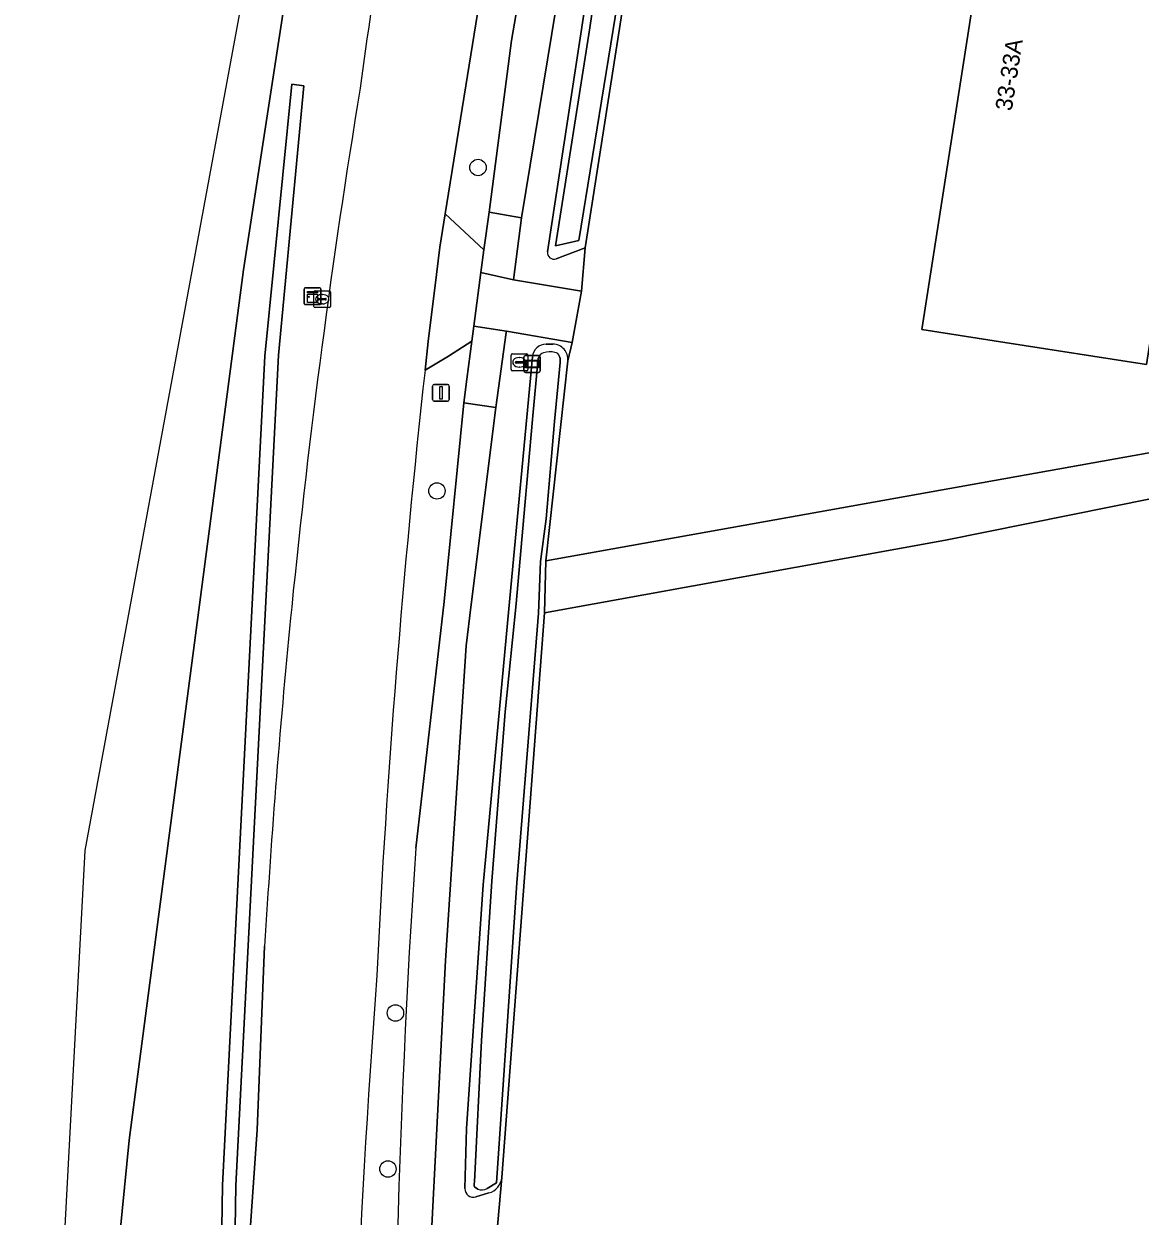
# Model space of a CAD drawing. Extents: x 162510 to 163918, y 388494 to 389774.
# Drawn here: x 162529.3 to 162595.9, y 389141.7 to 389212.7 of the extents above; entities that cross this region are included whole.
import ezdxf

# ---------------------------------------------------------------- set-up
doc = ezdxf.new("R2010")
doc.units = 0
for name, color, linetype in [('IMGEO_Berm_groen', 7, 'Continuous'), ('IMGEO_Boom', 7, 'Continuous'), ('IMGEO_Brandkraan', 7, 'Continuous'), ('IMGEO_Erf', 7, 'Continuous'), ('IMGEO_Fietspad_gesloten', 7, 'Continuous'), ('IMGEO_Fietspad_open', 7, 'Continuous'), ('IMGEO_Grasland_agrarisch', 7, 'Continuous'), ('IMGEO_Groenvoorziening', 7, 'Continuous'), ('IMGEO_Haag', 7, 'Continuous'), ('IMGEO_Kast', 7, 'Continuous'), ('IMGEO_Lichtmast', 7, 'Continuous'), ('IMGEO_Oever', 7, 'Continuous'), ('IMGEO_Pand', 7, 'Continuous'), ('IMGEO_Pand_nummerreeks', 7, 'Continuous'), ('IMGEO_Rijbaan_lokaal_gesloten', 7, 'Continuous'), ('IMGEO_Rijbaan_lokaal_open', 7, 'Continuous'), ('IMGEO_Rijbaan_regionaal_gesloten', 7, 'Continuous'), ('IMGEO_Rioolput', 7, 'Continuous'), ('IMGEO_Verklikker', 7, 'Continuous'), ('IMGEO_Voetpad_open', 7, 'Continuous'), ('IMGEO_Waterloop', 7, 'Continuous')]:
    doc.layers.add(name, color=color, linetype=linetype)

msp = doc.modelspace()

# ---------------------------------------------------------------- linework, layer by layer
at = {"layer": 'IMGEO_Berm_groen'}
for points in [[(162578.291, 389339.209), (162562.528, 389250), (162558.728, 389227.691), (162557.59, 389221.012), (162554.439, 389201.41), (162556.746, 389199.277), (162557.059, 389201.504), (162558.393, 389211.739), (162561.148, 389227.73), (162564.984, 389250), (162573.643, 389300.337), (162582.8, 389349.853), (162587.308, 389370.06), (162590.51, 389382)], [(162566.487, 389328.537), (162555.541, 389271.647), (162551.509, 389250), (162549.518, 389239.311), (162547.006, 389227.506), (162546.737, 389226.244), (162542.42, 389198.072), (162535.591, 389146.194), (162532.774, 389117.585), (162532.37, 389111.58), (162531.945, 389105.576), (162531.883, 389104.725), (162542.611, 389104.527), (162542.248, 389126.195), (162542.247, 389126.251), (162542.46, 389135.692), (162543.227, 389146.814)], [(162552.68, 389163.6), (162554.369, 389178.31), (162555.538, 389190.147), (162555.728, 389191.566), (162556.029, 389193.817), (162554.628, 389192.923), (162553.237, 389192.101)], [(162543.227, 389146.814), (162543.676, 389157.755)]]:
    msp.add_lwpolyline(points, dxfattribs=at)
msp.add_lwpolyline([(162545.297, 389209.14), (162546.015, 389209.041), (162544.5, 389192.998), (162541.965, 389143.494), (162541.527, 389115.616), (162541.714, 389107.47), (162540.915, 389107.452), (162540.727, 389115.614), (162541.165, 389143.52), (162543.695, 389192.921)], close=True, dxfattribs=at)
for centre, radius, start, end in [((163016.869, 389145.516), 471.78, 169.98165, 172.27762), ((163041.938, 389128.226), 499.136, 170.69731, 174.28081), ((163134.343, 389127.616), 584.673, 173.667779, 177.216056), ((163042.455, 389128.167), 499.656, 174.28008, 176.6052), ((163131.139, 389124.822), 579.757, 176.164852, 181.065754), ((163178.789, 389108.905), 630.192, 175.71308, 179.850847)]:
    msp.add_arc(centre, radius, start, end, dxfattribs=at)
at = {"layer": 'IMGEO_Boom'}
for centre in [(162556.393, 389204.175), (162553.946, 389184.898), (162551.472, 389153.78), (162551.024, 389144.481)]:
    msp.add_circle(centre, 0.489, dxfattribs=at)
at = {"layer": 'IMGEO_Brandkraan'}
for p, q in [((162558.36, 389192.136), (162558.36, 389192.988)), ((162558.435, 389193.062), (162559.287, 389193.062)), ((162558.662, 389192.605), (162559.06, 389192.605)), ((162558.848, 389192.842), (162558.873, 389192.842)), ((162559.361, 389192.988), (162559.361, 389192.136)), ((162559.287, 389192.062), (162558.435, 389192.062)), ((162558.619, 389192.556), (162558.619, 389192.568)), ((162559.057, 389192.519), (162558.659, 389192.519)), ((162558.871, 389192.282), (162558.846, 389192.282)), ((162559.103, 389192.568), (162559.103, 389192.556))]:
    msp.add_line(p, q, dxfattribs=at)
for points in [[(162558.36, 389192.136), (162558.36, 389192.988)], [(162558.435, 389193.062), (162559.287, 389193.062)], [(162559.361, 389192.988), (162559.361, 389192.136)], [(162559.287, 389192.062), (162558.435, 389192.062)]]:
    msp.add_lwpolyline(points, dxfattribs=at)
for centre, radius, start, end in [((162558.437, 389192.986), 0.0765, 91.55205, 178.44795), ((162558.437, 389192.986), 0.0765, 91.55205, 178.44795), ((162558.659, 389192.565), 0.0403, 85.87752, 175.75265), ((162559.064, 389192.567), 0.0386, 1.73085, 96.63898), ((162559.285, 389192.986), 0.0765, 1.55205, 88.44795), ((162559.285, 389192.986), 0.0765, 1.55205, 88.44795), ((162558.437, 389192.138), 0.0765, 181.55205, 268.44795), ((162558.437, 389192.138), 0.0765, 181.55205, 268.44795), ((162558.656, 389192.555), 0.0366, 178.93798, 274.71019), ((162559.06, 389192.562), 0.043, 264.86636, 352.45326), ((162559.285, 389192.138), 0.0765, 271.55205, 358.44795), ((162559.285, 389192.138), 0.0765, 271.55205, 358.44795)]:
    msp.add_arc(centre, radius, start, end, dxfattribs=at)
for centre, major_axis, ratio, start_param, end_param in [((162558.847, 389192.562), (-0.387, 0.002), 0.722429, 4.712389, 7.853982), ((162558.872, 389192.562), (-0.39, 0.002), 0.717154, 1.570796, 4.712389)]:
    msp.add_ellipse(centre, major_axis=major_axis, ratio=ratio, start_param=start_param, end_param=end_param, dxfattribs=at)
at = {"layer": 'IMGEO_Erf'}
msp.add_lwpolyline([(162571, 389230.043), (162570.831, 389229.366), (162570.5, 389228.374), (162570.367, 389228.01), (162569.475, 389228.043), (162568.35, 389227.448), (162567.424, 389226.985), (162567.013, 389226.448), (162562.784, 389199.385), (162562.558, 389196.812), (162562.318, 389195.488), (162562, 389193.735), (162561.745, 389192.655), (162560.443, 389180.721), (162604.045, 389188.547), (162613.107, 389191.215), (162635.908, 389194.267), (162680.291, 389202.531), (162722.247, 389210.612)], dxfattribs=at)
msp.add_lwpolyline([(162597.194, 389226.557), (162596.027, 389219.078), (162600.29, 389218.412), (162596.235, 389192.428), (162587.795, 389193.746), (162582.854, 389194.517), (162588.077, 389227.98), (162593.018, 389227.209)], close=True, dxfattribs=at)
at = {"layer": 'IMGEO_Fietspad_gesloten'}
msp.add_lwpolyline([(162590.51, 389382), (162587.308, 389370.06), (162582.8, 389349.853), (162573.643, 389300.337), (162564.984, 389250), (162561.148, 389227.73), (162558.393, 389211.739), (162557.059, 389201.504), (162558.98, 389201.185), (162563.35, 389227.764), (162563.969, 389231.546), (162564.383, 389234.079), (162566.987, 389250), (162579.655, 389322.796), (162581.07, 389329.832)], dxfattribs=at)
at = {"layer": 'IMGEO_Fietspad_open'}
msp.add_lwpolyline([(162558.98, 389201.185), (162557.059, 389201.504), (162556.746, 389199.277), (162556.555, 389197.917), (162558.504, 389197.478)], close=True, dxfattribs=at)
at = {"layer": 'IMGEO_Grasland_agrarisch'}
msp.add_lwpolyline([(162633.62, 389150.066), (162636.055, 389150.69), (162626.453, 389178.999), (162610.009, 389176.591), (162608.213, 389177.358), (162607.384, 389182.013), (162611.509, 389182.748), (162693.72, 389197.466), (162693.057, 389199.699), (162692.096, 389200.77), (162690.574, 389201.26), (162688.086, 389201.653), (162681.156, 389201.063), (162646.025, 389193.654), (162631.764, 389190.832), (162601.502, 389185.449), (162584.261, 389181.971), (162560.36, 389177.64), (162557.815, 389143.978), (162557.257, 389137.711), (162556.609, 389127.989), (162616.111, 389137.29), (162618.597, 389150.697), (162631.291, 389155.256)], close=True, dxfattribs=at)
at = {"layer": 'IMGEO_Groenvoorziening'}
for points in [[(162564.611, 389225.821), (162564.071, 389225.902), (162564.186, 389226.474), (162564.448, 389227.782), (162564.751, 389229.289), (162564.874, 389229.901), (162565.043, 389230.722), (162567.064, 389230.691), (162567.08, 389231.355), (162563.969, 389231.546), (162563.35, 389227.764), (162558.98, 389201.185), (162558.504, 389197.478), (162562.558, 389196.812), (162562.784, 389199.385), (162561.057, 389198.73)], [(162560.539, 389199.157), (162564.611, 389225.821)], [(162561.745, 389192.655), (162562, 389193.735), (162558.092, 389194.43), (162558.079, 389194.332), (162557.463, 389189.87), (162555.979, 389178.13), (162555.679, 389175.667), (162554.458, 389156.905), (162553.417, 389136.844), (162553.297, 389118.241), (162553.487, 389105.712), (162555.095, 389103.283), (162557.496, 389100.727), (162556.896, 389119.432)], [(162560.456, 389193.643), (162560.862, 389193.642)], [(162555.615, 389143.313), (162555.707, 389146.903), (162556.703, 389161.423), (162558.236, 389177.877), (162559.635, 389192.896)], [(162555.192, 389128.065), (162555.678, 389138.001), (162556.478, 389138.5), (162557.162, 389138.087), (162557.257, 389137.711), (162557.815, 389143.978)], [(162557.046, 389143.051), (162556.262, 389142.817)]]:
    msp.add_lwpolyline(points, dxfattribs=at)
msp.add_lwpolyline([(162546.015, 389209.041), (162545.297, 389209.14), (162543.695, 389192.921), (162541.165, 389143.52), (162540.727, 389115.614), (162540.915, 389107.452), (162541.714, 389107.47), (162541.527, 389115.616), (162541.965, 389143.494), (162544.5, 389192.998)], close=True, dxfattribs=at)
for centre, radius, start, end in [((162560.926, 389199.099), 0.391, 171.47328, 289.52754), ((162560.453, 389192.822), 0.821, 89.78523, 174.81076), ((162560.86, 389192.752), 0.89, 353.73945, 89.89411), ((162556.736, 389144.091), 1.085, 286.60113, 354.04354), ((162556.118, 389143.3), 0.504, 178.47715, 286.57421)]:
    msp.add_arc(centre, radius, start, end, dxfattribs=at)
at = {"layer": 'IMGEO_Haag'}
msp.add_lwpolyline([(162546.015, 389209.041), (162545.297, 389209.14), (162543.695, 389192.921), (162541.165, 389143.52), (162540.727, 389115.614), (162540.915, 389107.452), (162541.714, 389107.47), (162541.527, 389115.616), (162541.965, 389143.494), (162544.5, 389192.998)], close=True, dxfattribs=at)
at = {"layer": 'IMGEO_Kast'}
for p, q in [((162546.027, 389196.078), (162546.027, 389196.919)), ((162546.027, 389196.919), (162546.027, 389196.078)), ((162546.102, 389197.003), (162546.943, 389197.003)), ((162546.943, 389197.003), (162546.102, 389197.003)), ((162547.027, 389196.928), (162547.027, 389196.087)), ((162547.027, 389196.087), (162547.027, 389196.928)), ((162546.952, 389196.003), (162546.111, 389196.003)), ((162546.111, 389196.003), (162546.952, 389196.003))]:
    msp.add_line(p, q, dxfattribs=at)
for points in [[(162546.222, 389196.793), (162546.822, 389196.793), (162546.822, 389196.708), (162546.222, 389196.708), (162546.222, 389196.793)], [(162546.222, 389196.618), (162546.822, 389196.618), (162546.822, 389196.129), (162546.222, 389196.129), (162546.222, 389196.618)]]:
    msp.add_lwpolyline(points, dxfattribs=at)
msp.add_circle((162546.306, 389196.467), 0.0377, dxfattribs=at)
for centre, start, end in [((162546.105, 389196.925), 92.4484, 184.28452), ((162546.105, 389196.925), 92.4484, 184.28452), ((162546.949, 389196.925), 2.4484, 94.28452), ((162546.949, 389196.925), 2.4484, 94.28452), ((162546.105, 389196.081), 182.4484, 274.28452), ((162546.105, 389196.081), 182.4484, 274.28452), ((162546.949, 389196.081), 272.4484, 4.28452), ((162546.949, 389196.081), 272.4484, 4.28452)]:
    msp.add_arc(centre, 0.0779, start, end, dxfattribs=at)
at = {"layer": 'IMGEO_Lichtmast'}
for p, q in [((162553.789, 389191.241), (162554.579, 389191.241)), ((162554.579, 389191.241), (162553.789, 389191.241)), ((162553.689, 389190.341), (162553.689, 389191.141)), ((162553.689, 389191.141), (162553.689, 389190.341)), ((162554.679, 389191.141), (162554.679, 389190.341)), ((162554.679, 389190.341), (162554.679, 389191.141)), ((162554.579, 389190.241), (162553.789, 389190.241)), ((162553.789, 389190.241), (162554.579, 389190.241))]:
    msp.add_line(p, q, dxfattribs=at)
msp.add_lwpolyline([(162554.109, 389191.116), (162554.259, 389191.116), (162554.259, 389190.366), (162554.109, 389190.366), (162554.109, 389191.116)], dxfattribs=at)
for centre, start, end in [((162553.789, 389191.141), 90, 180), ((162553.789, 389191.141), 90, 180), ((162554.579, 389191.141), 0, 90), ((162554.579, 389191.141), 360, 90), ((162553.789, 389190.341), 180, 270), ((162553.789, 389190.341), 180, 270), ((162554.579, 389190.341), 270, 0), ((162554.579, 389190.341), 270, 0)]:
    msp.add_arc(centre, 0.1, start, end, dxfattribs=at)
at = {"layer": 'IMGEO_Oever'}
for points in [[(162562.784, 389199.385), (162567.013, 389226.448), (162566.368, 389226.279), (162564.837, 389214.855), (162562.403, 389199.83), (162561.019, 389199.499), (162563.054, 389212.499), (162564.518, 389222.44), (162565.075, 389225.942), (162564.611, 389225.821), (162560.539, 389199.157)], [(162561.057, 389198.73), (162562.784, 389199.385)], [(162560.862, 389193.642), (162560.456, 389193.643)], [(162559.635, 389192.896), (162558.236, 389177.877), (162556.703, 389161.423), (162555.707, 389146.903), (162555.615, 389143.313)], [(162556.385, 389143.284), (162556.185, 389143.417), (162556.159, 389143.483), (162556.156, 389143.596), (162556.175, 389143.719), (162556.595, 389152.139), (162557.207, 389161.642), (162558.018, 389171.736), (162558.666, 389178.158), (162559.133, 389183.346), (162559.639, 389189.162), (162559.985, 389192.802)], [(162561.258, 389192.912), (162561.282, 389192.782), (162561.29, 389192.56), (162560.956, 389189.042), (162560.451, 389183.229), (162560.126, 389180.682), (162559.991, 389177.602), (162558.702, 389161.547), (162558.168, 389153.596), (162557.497, 389143.654)], [(162560.36, 389177.64), (162560.443, 389180.721), (162561.745, 389192.655)], [(162557.815, 389143.978), (162560.36, 389177.64)], [(162557.497, 389143.654), (162556.93, 389143.324)], [(162556.262, 389142.817), (162557.046, 389143.051)]]:
    msp.add_lwpolyline(points, dxfattribs=at)
for centre, radius, start, end in [((162560.926, 389199.099), 0.391, 171.47328, 289.52754), ((162560.453, 389192.822), 0.821, 89.78523, 174.81076), ((162560.86, 389192.752), 0.89, 353.73945, 89.89411), ((162560.465, 389192.661), 0.5, 108.62344, 163.65756), ((162560.688, 389191.697), 1.488, 79.01543, 104.93444), ((162560.94, 389192.832), 0.328, 14.16187, 84.43786), ((162556.736, 389144.091), 1.085, 286.60113, 354.04354), ((162556.118, 389143.3), 0.504, 178.47715, 286.57421), ((162556.616, 389143.865), 0.626, 248.30522, 300.09012)]:
    msp.add_arc(centre, radius, start, end, dxfattribs=at)
at = {"layer": 'IMGEO_Pand'}
msp.add_lwpolyline([(162593.018, 389227.209), (162588.077, 389227.98), (162582.854, 389194.517), (162587.795, 389193.746), (162596.235, 389192.428), (162600.29, 389218.412), (162596.027, 389219.078), (162597.194, 389226.557)], close=True, dxfattribs=at)
at = {"layer": 'IMGEO_Rijbaan_lokaal_gesloten'}
for points in [[(162553.237, 389192.101), (162553.428, 389193.804), (162553.918, 389197.788), (162554.121, 389199.435), (162554.439, 389201.41), (162557.59, 389221.012), (162558.728, 389227.691), (162562.528, 389250), (162578.291, 389339.209)], [(162543.676, 389157.755), (162543.227, 389146.814), (162542.46, 389135.692), (162542.247, 389126.251), (162542.248, 389126.195), (162542.611, 389104.527), (162542.643, 389103.346), (162548.836, 389103.513), (162548.655, 389109.083), (162548.599, 389110.546)]]:
    msp.add_lwpolyline(points, dxfattribs=at)
for centre, radius, start, end in [((163016.869, 389145.516), 471.78, 169.98165, 172.27762), ((163041.938, 389128.226), 499.136, 170.69731, 174.28081), ((163134.343, 389127.616), 584.673, 173.667779, 177.216056), ((163042.455, 389128.167), 499.656, 174.28008, 176.6052), ((163178.789, 389108.905), 630.192, 175.71308, 179.850847)]:
    msp.add_arc(centre, radius, start, end, dxfattribs=at)
at = {"layer": 'IMGEO_Rijbaan_lokaal_open'}
for points in [[(162556.555, 389197.917), (162556.746, 389199.277), (162554.439, 389201.41), (162554.121, 389199.435), (162553.918, 389197.788), (162553.428, 389193.804), (162553.237, 389192.101), (162554.628, 389192.923), (162556.029, 389193.817), (162556.151, 389194.724)], [(162562.558, 389196.812), (162558.504, 389197.478), (162556.555, 389197.917), (162556.151, 389194.724), (162558.092, 389194.43), (162562, 389193.735), (162562.318, 389195.488)]]:
    msp.add_lwpolyline(points, close=True, dxfattribs=at)
at = {"layer": 'IMGEO_Rijbaan_regionaal_gesloten'}
msp.add_lwpolyline([(162561.104, 389315.915), (162532.949, 389163.461), (162529.369, 389095.844), (162529.323, 389094.968), (162531.162, 389094.886), (162531.883, 389104.725), (162531.945, 389105.576), (162532.37, 389111.58), (162532.774, 389117.585), (162535.591, 389146.194), (162542.42, 389198.072), (162546.737, 389226.244), (162547.006, 389227.506), (162549.518, 389239.311), (162551.509, 389250), (162555.541, 389271.647), (162566.487, 389328.537)], dxfattribs=at)
at = {"layer": 'IMGEO_Rioolput'}
for p, q in [((162546.606, 389195.9), (162546.606, 389196.752)), ((162546.681, 389196.826), (162547.533, 389196.826)), ((162546.865, 389196.32), (162546.865, 389196.332)), ((162547.303, 389196.283), (162546.905, 389196.283)), ((162546.908, 389196.369), (162547.306, 389196.369)), ((162547.094, 389196.606), (162547.119, 389196.606)), ((162547.349, 389196.332), (162547.349, 389196.32)), ((162547.607, 389196.752), (162547.607, 389195.9)), ((162547.533, 389195.826), (162546.681, 389195.826)), ((162547.117, 389196.046), (162547.092, 389196.046))]:
    msp.add_line(p, q, dxfattribs=at)
for points in [[(162546.606, 389195.9), (162546.606, 389196.752)], [(162546.681, 389196.826), (162547.533, 389196.826)], [(162547.607, 389196.752), (162547.607, 389195.9)], [(162547.533, 389195.826), (162546.681, 389195.826)]]:
    msp.add_lwpolyline(points, dxfattribs=at)
for centre, radius, start, end in [((162546.683, 389196.75), 0.0765, 91.55205, 178.44795), ((162546.683, 389196.75), 0.0765, 91.55205, 178.44795), ((162546.905, 389196.329), 0.0403, 85.87752, 175.75265), ((162546.902, 389196.319), 0.0366, 178.93798, 274.71019), ((162547.306, 389196.326), 0.043, 264.86636, 352.45326), ((162547.31, 389196.331), 0.0386, 1.73085, 96.63898), ((162547.531, 389196.75), 0.0765, 1.55205, 88.44795), ((162547.531, 389196.75), 0.0765, 1.55205, 88.44795), ((162546.683, 389195.902), 0.0765, 181.55205, 268.44795), ((162546.683, 389195.902), 0.0765, 181.55205, 268.44795), ((162547.531, 389195.902), 0.0765, 271.55205, 358.44795), ((162547.531, 389195.902), 0.0765, 271.55205, 358.44795)]:
    msp.add_arc(centre, radius, start, end, dxfattribs=at)
for centre, major_axis, ratio, start_param, end_param in [((162547.093, 389196.326), (-0.387, 0.002), 0.722429, 4.712389, 7.853982), ((162547.118, 389196.326), (-0.39, 0.002), 0.717154, 1.570796, 4.712389)]:
    msp.add_ellipse(centre, major_axis=major_axis, ratio=ratio, start_param=start_param, end_param=end_param, dxfattribs=at)
at = {"layer": 'IMGEO_Verklikker'}
for p, q in [((162559.116, 389192.062), (162559.116, 389192.862)), ((162559.116, 389192.862), (162559.116, 389192.062)), ((162559.216, 389192.962), (162560.006, 389192.962)), ((162560.006, 389192.962), (162559.216, 389192.962)), ((162560.106, 389192.862), (162560.106, 389192.062)), ((162560.106, 389192.062), (162560.106, 389192.862)), ((162560.006, 389191.962), (162559.216, 389191.962)), ((162559.216, 389191.962), (162560.006, 389191.962))]:
    msp.add_line(p, q, dxfattribs=at)
for points in [[(162559.217, 389192.694), (162560.005, 389192.694), (162560.005, 389192.23), (162559.217, 389192.23), (162559.217, 389192.694)], [(162559.282, 389192.629), (162559.282, 389192.295), (162559.94, 389192.295), (162559.94, 389192.629), (162559.282, 389192.629)]]:
    msp.add_lwpolyline(points, dxfattribs=at)
for centre, start, end in [((162559.216, 389192.862), 90, 180), ((162559.216, 389192.862), 90, 180), ((162560.006, 389192.862), 0, 90), ((162560.006, 389192.862), 360, 90), ((162559.216, 389192.062), 180, 270), ((162559.216, 389192.062), 180, 270), ((162560.006, 389192.062), 270, 0), ((162560.006, 389192.062), 270, 0)]:
    msp.add_arc(centre, 0.1, start, end, dxfattribs=at)
at = {"layer": 'IMGEO_Voetpad_open'}
msp.add_lwpolyline([(162558.079, 389194.332), (162558.092, 389194.43), (162556.151, 389194.724), (162556.029, 389193.817), (162555.728, 389191.566), (162555.538, 389190.147), (162557.463, 389189.87)], close=True, dxfattribs=at)
msp.add_lwpolyline([(162553.417, 389136.844), (162554.458, 389156.905), (162555.679, 389175.667), (162555.979, 389178.13), (162557.463, 389189.87), (162555.538, 389190.147), (162554.369, 389178.31), (162552.68, 389163.6)], dxfattribs=at)
msp.add_arc((163131.139, 389124.822), 579.757, 176.164852, 181.065754, dxfattribs=at)
at = {"layer": 'IMGEO_Waterloop'}
msp.add_lwpolyline([(162566.368, 389226.279), (162565.075, 389225.942), (162564.518, 389222.44), (162563.054, 389212.499), (162561.019, 389199.499), (162562.403, 389199.83), (162564.837, 389214.855)], close=True, dxfattribs=at)
for points in [[(162722.247, 389210.612), (162680.291, 389202.531), (162635.908, 389194.267), (162613.107, 389191.215), (162604.045, 389188.547), (162560.443, 389180.721), (162560.36, 389177.64), (162584.261, 389181.971), (162601.502, 389185.449), (162631.764, 389190.832), (162646.025, 389193.654)], [(162559.985, 389192.802), (162559.639, 389189.162), (162559.133, 389183.346), (162558.666, 389178.158), (162558.018, 389171.736), (162557.207, 389161.642), (162556.595, 389152.139), (162556.175, 389143.719), (162556.156, 389143.596), (162556.159, 389143.483), (162556.185, 389143.417), (162556.385, 389143.284)], [(162561.29, 389192.56), (162561.282, 389192.782), (162561.258, 389192.912)], [(162556.93, 389143.324), (162557.497, 389143.654), (162558.168, 389153.596), (162558.702, 389161.547), (162559.991, 389177.602), (162560.126, 389180.682), (162560.451, 389183.229), (162560.956, 389189.042), (162561.29, 389192.56)]]:
    msp.add_lwpolyline(points, dxfattribs=at)
for centre, radius, start, end in [((162560.465, 389192.661), 0.5, 108.62344, 163.65756), ((162560.688, 389191.697), 1.488, 79.01543, 104.93444), ((162560.94, 389192.832), 0.328, 14.16187, 84.43786), ((162556.616, 389143.865), 0.626, 248.30522, 300.09012)]:
    msp.add_arc(centre, radius, start, end, dxfattribs=at)

# ---------------------------------------------------------------- texts
at = {"layer": 'IMGEO_Pand_nummerreeks'}
msp.add_text('33-33A', height=1, rotation=81.12869, dxfattribs=at).set_placement((162588.201, 389207.503))

doc.saveas('drawing.dxf')
